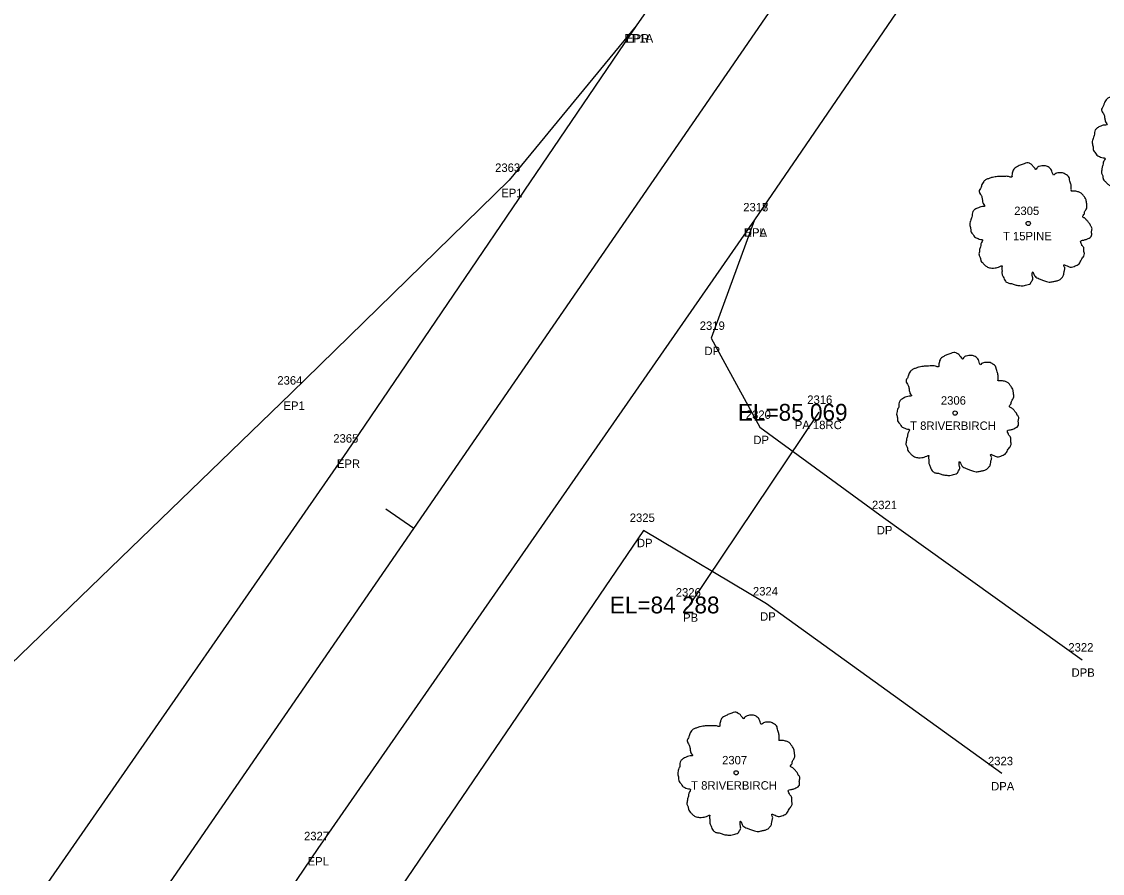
# Model space of a CAD drawing. Extents: x 2266664 to 2272542, y 716533 to 724777.
# Drawn here: x 2271445.4 to 2271573.7, y 723459.5 to 723560.6 of the extents above; entities that cross this region are included whole.
import ezdxf

# ---------------------------------------------------------------- set-up
doc = ezdxf.new("R2010")
doc.units = 0
for name, color, linetype in [('RD_EX_DR_Pipe', 7, 'Continuous'), ('RD_EX_DR_Pipe_txCode', 7, 'Continuous'), ('RD_EX_Driveway', 7, 'Continuous'), ('RD_EX_Driveway_txCode', 7, 'Continuous'), ('RD_EX_Road', 7, 'Continuous'), ('RD_EX_Road_txCode', 7, 'Continuous'), ('RD_EX_VEG', 7, 'Continuous'), ('RD_EX_VEG_txCode', 7, 'Continuous'), ('RD_HC_Cl', 7, 'Continuous'), ('RD_HC_Data_Tic', 7, 'Continuous'), ('RD_SMD_Locator', 7, 'Continuous'), ('RD_TX_Pipe_ElevEX', 7, 'Continuous')]:
    doc.layers.add(name, color=color, linetype=linetype)

msp = doc.modelspace()

# ---------------------------------------------------------------- linework, layer by layer
at = {"layer": 'RD_EX_DR_Pipe'}
msp.add_line((2271540, 723514.24), (2271524.67, 723491.36), dxfattribs=at)
at = {"layer": 'RD_EX_Driveway'}
for points in [[(2271532.38, 723537.1), (2271527.21, 723523.03), (2271533.01, 723512.46), (2271547.66, 723501.74), (2271571.25, 723484.83)], [(2271561.71, 723471.33), (2271533.81, 723491.49), (2271519.19, 723500.22), (2271489.22, 723456.09), (2271462.24, 723415.94), (2271476.12, 723404.59), (2271469.28, 723395.41), (2271454.17, 723403.69), (2271433.28, 723379.57), (2271407.1, 723356.2)]]:
    msp.add_lwpolyline(points, dxfattribs=at)
at = {"layer": 'RD_EX_Road'}
for points in [[(2271604.53, 723684.77), (2271550.65, 723606.61), (2271518.33, 723560.15), (2271484.03, 723509.64), (2271377.45, 723356.07), (2271354.74, 723322.34), (2271292.52, 723232.43), (2271237.2, 723151.69), (2271183.29, 723072.86), (2271144.18, 723016.57), (2271140.21, 723010.22), (2271130.75, 722996.02)], [(2271614.21, 723655.35), (2271570.62, 723593.07), (2271532.38, 723537.1), (2271480.53, 723462.42), (2271443.77, 723408.17), (2271407.1, 723356.2), (2271374.69, 723308.79), (2271312.42, 723217.53), (2271256.65, 723136.94), (2271202.38, 723058.06), (2271164.68, 723002.43), (2271160.3, 722996.7), (2271150.37, 722982.5)], [(2271518.33, 723560.15), (2271503.23, 723541.79), (2271477.38, 723516.53), (2271382.08, 723424.38), (2271375.15, 723414.07), (2271383.23, 723378.71), (2271377.45, 723356.07)]]:
    msp.add_lwpolyline(points, dxfattribs=at)
at = {"layer": 'RD_EX_VEG'}
for centre, radius in [((2271564.86, 723536.67), 0.25), ((2271564.85, 723536.65), 0.0001), ((2271556.18, 723514.15), 0.25), ((2271556.17, 723514.13), 0.0001), ((2271530.19, 723471.43), 0.25), ((2271530.17, 723471.41), 0.0001)]:
    msp.add_circle(centre, radius, dxfattribs=at)
for points in [[(2271579.52, 723553.53), (2271579.22, 723553.55), (2271578.89, 723553.45), (2271578.64, 723553.35), (2271578.42, 723553.28), (2271578.19, 723553.18), (2271577.89, 723553), (2271577.67, 723552.8), (2271577.54, 723552.55), (2271577.49, 723552.33), (2271577.44, 723552.05), (2271577.44, 723551.88), (2271577.32, 723551.85), (2271577.17, 723551.88), (2271576.92, 723551.95), (2271576.67, 723551.95), (2271576.42, 723551.95), (2271576.07, 723551.93), (2271575.72, 723551.93), (2271575.45, 723551.88), (2271575.12, 723551.83), (2271574.75, 723551.7), (2271574.4, 723551.58), (2271574.1, 723551.33), (2271573.85, 723550.85), (2271573.72, 723550.5), (2271573.57, 723550.25), (2271573.72, 723549.8), (2271573.9, 723549.45), (2271573.92, 723549.25), (2271574, 723548.83), (2271574.1, 723548.61), (2271574.22, 723548.41), (2271574.15, 723548.38), (2271573.77, 723548.33), (2271573.47, 723548.23), (2271573.05, 723548.01), (2271572.82, 723547.78), (2271572.72, 723547.46), (2271572.7, 723547.11), (2271572.6, 723546.91), (2271572.52, 723546.63), (2271572.5, 723546.56), (2271572.45, 723546.23), (2271572.55, 723545.78), (2271572.57, 723545.43), (2271572.7, 723545.21), (2271572.85, 723545.03), (2271573.02, 723544.78), (2271573.42, 723544.56), (2271573.75, 723544.46), (2271573.95, 723544.43), (2271573.77, 723543.93), (2271573.72, 723543.58), (2271573.6, 723543.18), (2271573.6, 723543.11), (2271573.55, 723542.63), (2271573.7, 723542.31), (2271573.77, 723541.93), (2271573.95, 723541.71), (2271574.22, 723541.41), (2271574.55, 723541.18), (2271575.05, 723541.06), (2271575.45, 723541.08), (2271576.02, 723541.26), (2271576.27, 723541.33), (2271576.25, 723541.16), (2271576.27, 723540.78), (2271576.27, 723540.36), (2271576.42, 723540.03), (2271576.52, 723539.76), (2271576.67, 723539.51), (2271577, 723539.28), (2271577.39, 723539.21), (2271577.82, 723539.06), (2271578.27, 723538.98), (2271578.77, 723538.96), (2271579.37, 723539.11), (2271579.64, 723539.23), (2271579.74, 723539.41), (2271579.94, 723539.78), (2271579.89, 723540.01), (2271579.92, 723540.61), (2271580.02, 723540.43), (2271580.19, 723540.08), (2271580.69, 723539.78), (2271581.09, 723539.61), (2271581.57, 723539.46), (2271581.87, 723539.38), (2271582.34, 723539.46), (2271582.72, 723539.53), (2271583.09, 723539.66), (2271583.39, 723539.93), (2271583.57, 723540.21), (2271583.62, 723540.48), (2271583.69, 723540.86), (2271583.74, 723541.03)], [(2271565, 723543.84), (2271564.7, 723543.86), (2271564.37, 723543.76), (2271564.12, 723543.66), (2271563.9, 723543.59), (2271563.67, 723543.49), (2271563.37, 723543.31), (2271563.15, 723543.11), (2271563.02, 723542.86), (2271562.97, 723542.64), (2271562.92, 723542.36), (2271562.92, 723542.19), (2271562.8, 723542.16), (2271562.65, 723542.19), (2271562.4, 723542.26), (2271562.15, 723542.26), (2271561.9, 723542.26), (2271561.55, 723542.24), (2271561.2, 723542.24), (2271560.92, 723542.19), (2271560.6, 723542.14), (2271560.22, 723542.01), (2271559.87, 723541.89), (2271559.57, 723541.64), (2271559.32, 723541.17), (2271559.2, 723540.82), (2271559.05, 723540.57), (2271559.2, 723540.12), (2271559.37, 723539.77), (2271559.4, 723539.57), (2271559.47, 723539.14), (2271559.57, 723538.92), (2271559.7, 723538.72), (2271559.62, 723538.69), (2271559.25, 723538.64), (2271558.95, 723538.54), (2271558.52, 723538.32), (2271558.3, 723538.09), (2271558.2, 723537.77), (2271558.17, 723537.42), (2271558.07, 723537.22), (2271558, 723536.94), (2271557.97, 723536.87), (2271557.92, 723536.54), (2271558.02, 723536.09), (2271558.05, 723535.74), (2271558.17, 723535.52), (2271558.32, 723535.34), (2271558.5, 723535.09), (2271558.9, 723534.87), (2271559.22, 723534.77), (2271559.42, 723534.74), (2271559.25, 723534.24), (2271559.2, 723533.89), (2271559.07, 723533.49), (2271559.07, 723533.42), (2271559.02, 723532.94), (2271559.17, 723532.62), (2271559.25, 723532.24), (2271559.42, 723532.02), (2271559.7, 723531.72), (2271560.02, 723531.49), (2271560.52, 723531.37), (2271560.92, 723531.39), (2271561.5, 723531.57), (2271561.75, 723531.64), (2271561.72, 723531.47), (2271561.75, 723531.09), (2271561.75, 723530.67), (2271561.9, 723530.34), (2271562, 723530.07), (2271562.15, 723529.82), (2271562.47, 723529.6), (2271562.87, 723529.52), (2271563.3, 723529.37), (2271563.75, 723529.3), (2271564.25, 723529.27), (2271564.85, 723529.42), (2271565.12, 723529.55), (2271565.22, 723529.72), (2271565.42, 723530.09), (2271565.37, 723530.32), (2271565.4, 723530.92), (2271565.5, 723530.74), (2271565.67, 723530.39), (2271566.17, 723530.09), (2271566.57, 723529.92), (2271567.04, 723529.77), (2271567.34, 723529.7), (2271567.82, 723529.77), (2271568.19, 723529.84), (2271568.57, 723529.97), (2271568.87, 723530.24), (2271569.04, 723530.52), (2271569.09, 723530.79), (2271569.17, 723531.17), (2271569.22, 723531.34)], [(2271569.22, 723531.34), (2271569.14, 723531.52), (2271569.09, 723531.77), (2271569.17, 723531.74), (2271569.34, 723531.69), (2271569.62, 723531.57), (2271569.84, 723531.49), (2271570.17, 723531.52), (2271570.44, 723531.62), (2271570.89, 723531.89), (2271571.17, 723532.37), (2271571.44, 723532.77), (2271571.52, 723533.09), (2271571.47, 723533.32), (2271571.44, 723533.82), (2271571.24, 723534.07), (2271571.19, 723534.19), (2271571.09, 723534.59), (2271571.17, 723534.64), (2271571.44, 723534.69), (2271571.82, 723534.82), (2271572.09, 723534.94), (2271572.32, 723535.12), (2271572.39, 723535.34), (2271572.37, 723535.74), (2271572.42, 723536.14), (2271572.34, 723536.29), (2271572.24, 723536.44), (2271572.17, 723536.64), (2271572.02, 723536.79), (2271571.92, 723536.94), (2271571.82, 723537.04), (2271571.69, 723537.19), (2271571.52, 723537.32), (2271571.37, 723537.37), (2271571.32, 723537.52), (2271571.47, 723537.72), (2271571.52, 723537.82), (2271571.54, 723538.04), (2271571.77, 723538.39), (2271571.82, 723538.79), (2271571.77, 723539.22), (2271571.72, 723539.49), (2271571.57, 723539.77), (2271571.37, 723540.02), (2271571.24, 723540.19), (2271571.07, 723540.32), (2271570.74, 723540.44), (2271570.49, 723540.49), (2271570.14, 723540.49), (2271569.94, 723540.54), (2271569.97, 723540.59), (2271569.97, 723540.74), (2271569.97, 723541.02), (2271569.89, 723541.46), (2271569.74, 723541.96), (2271569.74, 723541.99), (2271569.64, 723542.24), (2271569.42, 723542.44), (2271569.24, 723542.54), (2271569.04, 723542.66), (2271568.79, 723542.69), (2271568.49, 723542.69), (2271568.22, 723542.64), (2271568.02, 723542.54), (2271567.84, 723542.41), (2271567.77, 723542.56), (2271567.67, 723542.86), (2271567.62, 723543.01), (2271567.47, 723543.19), (2271567.24, 723543.39), (2271566.79, 723543.51), (2271566.17, 723543.44), (2271565.87, 723543.24), (2271565.72, 723543.06), (2271565.67, 723543.19), (2271565.47, 723543.39), (2271565.37, 723543.56), (2271565.2, 723543.69), (2271565.05, 723543.79), (2271564.95, 723543.84)], [(2271556.31, 723521.32), (2271556.01, 723521.34), (2271555.69, 723521.24), (2271555.44, 723521.14), (2271555.21, 723521.07), (2271554.99, 723520.97), (2271554.69, 723520.79), (2271554.46, 723520.59), (2271554.34, 723520.34), (2271554.29, 723520.12), (2271554.24, 723519.84), (2271554.24, 723519.67), (2271554.11, 723519.64), (2271553.96, 723519.67), (2271553.71, 723519.74), (2271553.46, 723519.74), (2271553.21, 723519.74), (2271552.86, 723519.72), (2271552.51, 723519.72), (2271552.24, 723519.67), (2271551.91, 723519.62), (2271551.54, 723519.49), (2271551.19, 723519.37), (2271550.89, 723519.12), (2271550.64, 723518.64), (2271550.51, 723518.29), (2271550.36, 723518.04), (2271550.51, 723517.59), (2271550.69, 723517.24), (2271550.71, 723517.04), (2271550.79, 723516.62), (2271550.89, 723516.39), (2271551.01, 723516.19), (2271550.94, 723516.17), (2271550.56, 723516.12), (2271550.26, 723516.02), (2271549.84, 723515.79), (2271549.61, 723515.57), (2271549.51, 723515.24), (2271549.49, 723514.89), (2271549.39, 723514.69), (2271549.31, 723514.42), (2271549.29, 723514.34), (2271549.24, 723514.02), (2271549.34, 723513.57), (2271549.36, 723513.22), (2271549.49, 723512.99), (2271549.64, 723512.82), (2271549.81, 723512.57), (2271550.21, 723512.34), (2271550.54, 723512.24), (2271550.74, 723512.22), (2271550.56, 723511.72), (2271550.51, 723511.37), (2271550.39, 723510.97), (2271550.39, 723510.89), (2271550.34, 723510.42), (2271550.49, 723510.09), (2271550.56, 723509.72), (2271550.74, 723509.5), (2271551.01, 723509.2), (2271551.34, 723508.97), (2271551.84, 723508.85), (2271552.24, 723508.87), (2271552.81, 723509.05), (2271553.06, 723509.12), (2271553.04, 723508.95), (2271553.06, 723508.57), (2271553.06, 723508.15), (2271553.21, 723507.82), (2271553.31, 723507.55), (2271553.46, 723507.3), (2271553.79, 723507.07), (2271554.19, 723507), (2271554.61, 723506.85), (2271555.06, 723506.77), (2271555.56, 723506.75), (2271556.16, 723506.9), (2271556.44, 723507.02), (2271556.54, 723507.2), (2271556.74, 723507.57), (2271556.69, 723507.8), (2271556.71, 723508.4), (2271556.81, 723508.22), (2271556.99, 723507.87), (2271557.49, 723507.57), (2271557.89, 723507.4), (2271558.36, 723507.25), (2271558.66, 723507.17), (2271559.14, 723507.25), (2271559.51, 723507.32), (2271559.88, 723507.45), (2271560.18, 723507.72), (2271560.36, 723508), (2271560.41, 723508.27), (2271560.48, 723508.65), (2271560.53, 723508.82)], [(2271560.53, 723508.82), (2271560.46, 723509), (2271560.41, 723509.25), (2271560.48, 723509.22), (2271560.66, 723509.17), (2271560.93, 723509.05), (2271561.16, 723508.97), (2271561.48, 723509), (2271561.76, 723509.1), (2271562.21, 723509.37), (2271562.48, 723509.85), (2271562.76, 723510.24), (2271562.83, 723510.57), (2271562.78, 723510.79), (2271562.76, 723511.29), (2271562.56, 723511.54), (2271562.51, 723511.67), (2271562.41, 723512.07), (2271562.48, 723512.12), (2271562.76, 723512.17), (2271563.13, 723512.29), (2271563.41, 723512.42), (2271563.63, 723512.59), (2271563.71, 723512.82), (2271563.68, 723513.22), (2271563.73, 723513.62), (2271563.66, 723513.77), (2271563.56, 723513.92), (2271563.48, 723514.12), (2271563.33, 723514.27), (2271563.23, 723514.42), (2271563.13, 723514.52), (2271563.01, 723514.67), (2271562.83, 723514.79), (2271562.68, 723514.84), (2271562.63, 723514.99), (2271562.78, 723515.19), (2271562.83, 723515.29), (2271562.86, 723515.52), (2271563.08, 723515.87), (2271563.13, 723516.27), (2271563.08, 723516.69), (2271563.03, 723516.97), (2271562.88, 723517.24), (2271562.68, 723517.49), (2271562.56, 723517.67), (2271562.38, 723517.79), (2271562.06, 723517.92), (2271561.81, 723517.97), (2271561.46, 723517.97), (2271561.26, 723518.02), (2271561.28, 723518.07), (2271561.28, 723518.22), (2271561.28, 723518.49), (2271561.21, 723518.94), (2271561.06, 723519.44), (2271561.06, 723519.47), (2271560.96, 723519.72), (2271560.73, 723519.92), (2271560.56, 723520.02), (2271560.36, 723520.14), (2271560.11, 723520.17), (2271559.81, 723520.17), (2271559.53, 723520.12), (2271559.33, 723520.02), (2271559.16, 723519.89), (2271559.09, 723520.04), (2271558.99, 723520.34), (2271558.94, 723520.49), (2271558.79, 723520.67), (2271558.56, 723520.87), (2271558.11, 723520.99), (2271557.49, 723520.92), (2271557.19, 723520.72), (2271557.04, 723520.54), (2271556.99, 723520.67), (2271556.79, 723520.87), (2271556.69, 723521.04), (2271556.51, 723521.17), (2271556.36, 723521.27), (2271556.26, 723521.32)], [(2271530.32, 723478.59), (2271530.02, 723478.62), (2271529.69, 723478.52), (2271529.44, 723478.42), (2271529.22, 723478.34), (2271528.99, 723478.24), (2271528.69, 723478.07), (2271528.47, 723477.87), (2271528.34, 723477.62), (2271528.29, 723477.4), (2271528.24, 723477.12), (2271528.24, 723476.95), (2271528.12, 723476.92), (2271527.97, 723476.95), (2271527.72, 723477.02), (2271527.47, 723477.02), (2271527.22, 723477.02), (2271526.87, 723477), (2271526.52, 723477), (2271526.24, 723476.95), (2271525.92, 723476.9), (2271525.54, 723476.77), (2271525.19, 723476.65), (2271524.89, 723476.4), (2271524.64, 723475.92), (2271524.52, 723475.57), (2271524.37, 723475.32), (2271524.52, 723474.87), (2271524.69, 723474.52), (2271524.72, 723474.32), (2271524.79, 723473.9), (2271524.89, 723473.67), (2271525.02, 723473.47), (2271524.94, 723473.45), (2271524.57, 723473.4), (2271524.27, 723473.3), (2271523.85, 723473.07), (2271523.62, 723472.85), (2271523.52, 723472.52), (2271523.5, 723472.17), (2271523.4, 723471.97), (2271523.32, 723471.7), (2271523.3, 723471.62), (2271523.25, 723471.3), (2271523.35, 723470.85), (2271523.37, 723470.5), (2271523.5, 723470.27), (2271523.65, 723470.1), (2271523.82, 723469.85), (2271524.22, 723469.62), (2271524.54, 723469.52), (2271524.74, 723469.5), (2271524.57, 723469), (2271524.52, 723468.65), (2271524.4, 723468.25), (2271524.4, 723468.17), (2271524.35, 723467.7), (2271524.49, 723467.37), (2271524.57, 723467), (2271524.74, 723466.77), (2271525.02, 723466.47), (2271525.34, 723466.25), (2271525.84, 723466.13), (2271526.24, 723466.15), (2271526.82, 723466.32), (2271527.07, 723466.4), (2271527.04, 723466.23), (2271527.07, 723465.85), (2271527.07, 723465.43), (2271527.22, 723465.1), (2271527.32, 723464.83), (2271527.47, 723464.58), (2271527.79, 723464.35), (2271528.19, 723464.28), (2271528.62, 723464.13), (2271529.07, 723464.05), (2271529.57, 723464.03), (2271530.17, 723464.18), (2271530.44, 723464.3), (2271530.54, 723464.48), (2271530.74, 723464.85), (2271530.69, 723465.08), (2271530.72, 723465.68), (2271530.82, 723465.5), (2271530.99, 723465.15), (2271531.49, 723464.85), (2271531.89, 723464.68), (2271532.37, 723464.53), (2271532.67, 723464.45), (2271533.14, 723464.53), (2271533.52, 723464.6), (2271533.89, 723464.73), (2271534.19, 723465), (2271534.37, 723465.28), (2271534.42, 723465.55), (2271534.49, 723465.93), (2271534.54, 723466.1)], [(2271534.54, 723466.1), (2271534.47, 723466.28), (2271534.42, 723466.52), (2271534.49, 723466.5), (2271534.67, 723466.45), (2271534.94, 723466.32), (2271535.17, 723466.25), (2271535.49, 723466.28), (2271535.77, 723466.37), (2271536.21, 723466.65), (2271536.49, 723467.12), (2271536.76, 723467.52), (2271536.84, 723467.85), (2271536.79, 723468.07), (2271536.76, 723468.57), (2271536.56, 723468.82), (2271536.51, 723468.95), (2271536.41, 723469.35), (2271536.49, 723469.4), (2271536.76, 723469.45), (2271537.14, 723469.57), (2271537.41, 723469.7), (2271537.64, 723469.87), (2271537.71, 723470.1), (2271537.69, 723470.5), (2271537.74, 723470.9), (2271537.66, 723471.05), (2271537.56, 723471.2), (2271537.49, 723471.4), (2271537.34, 723471.55), (2271537.24, 723471.7), (2271537.14, 723471.8), (2271537.01, 723471.95), (2271536.84, 723472.07), (2271536.69, 723472.12), (2271536.64, 723472.27), (2271536.79, 723472.47), (2271536.84, 723472.57), (2271536.86, 723472.8), (2271537.09, 723473.15), (2271537.14, 723473.55), (2271537.09, 723473.97), (2271537.04, 723474.25), (2271536.89, 723474.52), (2271536.69, 723474.77), (2271536.56, 723474.95), (2271536.39, 723475.07), (2271536.06, 723475.2), (2271535.82, 723475.25), (2271535.47, 723475.25), (2271535.27, 723475.3), (2271535.29, 723475.35), (2271535.29, 723475.5), (2271535.29, 723475.77), (2271535.22, 723476.22), (2271535.07, 723476.72), (2271535.07, 723476.75), (2271534.97, 723477), (2271534.74, 723477.2), (2271534.57, 723477.3), (2271534.37, 723477.42), (2271534.12, 723477.45), (2271533.82, 723477.45), (2271533.54, 723477.4), (2271533.34, 723477.3), (2271533.17, 723477.17), (2271533.09, 723477.32), (2271532.99, 723477.62), (2271532.94, 723477.77), (2271532.79, 723477.94), (2271532.57, 723478.14), (2271532.12, 723478.27), (2271531.49, 723478.19), (2271531.19, 723477.99), (2271531.04, 723477.82), (2271530.99, 723477.94), (2271530.79, 723478.14), (2271530.69, 723478.32), (2271530.52, 723478.44), (2271530.37, 723478.54), (2271530.27, 723478.59)]]:
    msp.add_spline(points, degree=3, dxfattribs=at)
at = {"layer": 'RD_HC_Cl'}
msp.add_line((2267342.91, 717471.2), (2272360.46, 724762.59), dxfattribs=at)
at = {"layer": 'RD_HC_Data_Tic'}
msp.add_line((2271491.92, 723500.45), (2271488.62, 723502.72), dxfattribs=at)
at = {"layer": 'RD_SMD_Locator'}
for centre in [(2271518.33, 723560.15), (2271518.33, 723560.15), (2271503.23, 723541.79), (2271532.38, 723537.1), (2271532.38, 723537.1), (2271527.21, 723523.03), (2271477.38, 723516.53), (2271540, 723514.24), (2271533.01, 723512.46), (2271484.03, 723509.64), (2271547.66, 723501.74), (2271519.19, 723500.22), (2271524.67, 723491.36), (2271533.81, 723491.49), (2271571.25, 723484.83), (2271561.71, 723471.33), (2271480.53, 723462.42)]:
    msp.add_circle(centre, 0.001, dxfattribs=at)

# ---------------------------------------------------------------- texts
at = {"layer": 'RD_EX_DR_Pipe_txCode'}
for s, p in [('2316', (2271538.63, 723515.24)), ('PA 18RC', (2271537.15, 723512.24)), ('2326', (2271523.02, 723492.36)), ('PB', (2271523.89, 723489.36))]:
    msp.add_text(s, height=1, dxfattribs=at).set_placement(p)
at = {"layer": 'RD_EX_Driveway_txCode'}
for s, p in [('2318', (2271531.03, 723538.1)), ('DPA', (2271531.11, 723535.1)), ('2319', (2271525.87, 723524.03)), ('DP', (2271526.43, 723521.03)), ('2320', (2271531.34, 723513.46)), ('DP', (2271532.23, 723510.46)), ('2321', (2271546.31, 723502.74)), ('2325', (2271517.56, 723501.22)), ('DP', (2271546.88, 723499.74)), ('DP', (2271518.41, 723498.22)), ('2324', (2271532.18, 723492.49)), ('DP', (2271533.03, 723489.49)), ('2322', (2271569.62, 723485.83)), ('DPB', (2271570, 723482.83)), ('2323', (2271560.08, 723472.33)), ('DPA', (2271560.45, 723469.33))]:
    msp.add_text(s, height=1, dxfattribs=at).set_placement(p)
at = {"layer": 'RD_EX_Road_txCode'}
for s, p in [('EP1A', (2271516.92, 723558.15)), ('EPR', (2271517.1, 723558.15)), ('2363', (2271501.58, 723542.79)), ('EP1', (2271502.31, 723539.79)), ('2317', (2271531.03, 723538.1)), ('EPL', (2271531.17, 723535.1)), ('2364', (2271475.73, 723517.53)), ('EP1', (2271476.46, 723514.53)), ('2365', (2271482.37, 723510.64)), ('EPR', (2271482.8, 723507.64)), ('2327', (2271478.9, 723463.42)), ('EPL', (2271479.33, 723460.42))]:
    msp.add_text(s, height=1, dxfattribs=at).set_placement(p)
at = {"layer": 'RD_EX_VEG_txCode'}
for s, p in [('2305', (2271563.19, 723537.67)), ('T 15PINE', (2271561.86, 723534.67)), ('2306', (2271554.49, 723515.15)), ('T 8RIVERBIRCH', (2271550.84, 723512.15)), ('2307', (2271528.52, 723472.43)), ('T 8RIVERBIRCH', (2271524.85, 723469.43))]:
    msp.add_text(s, height=1, dxfattribs=at).set_placement(p)
at = {"layer": 'RD_TX_Pipe_ElevEX'}
for s, p in [('EL=85 069  ', (2271530.4, 723513.24)), ('EL=84 288  ', (2271515.2, 723490.36))]:
    msp.add_text(s, height=2, dxfattribs=at).set_placement(p)

doc.saveas('drawing.dxf')
